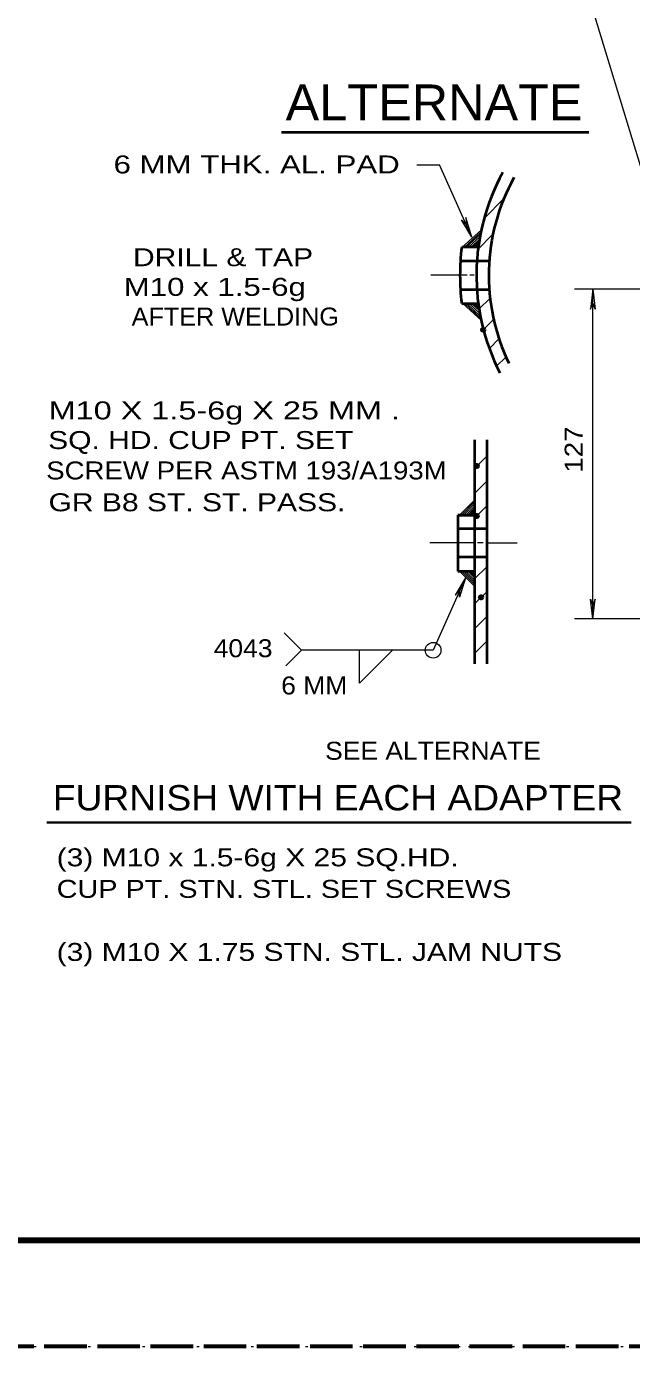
# Model space of a CAD drawing. Extents: x 312583 to 312854, y 144419 to 144597.
# Drawn here: x 312617.4 to 312643.1, y 144418.6 to 144474.4 of the extents above; entities that cross this region are included whole.
import ezdxf
from ezdxf.enums import TextEntityAlignment as Align

# ---------------------------------------------------------------- set-up
doc = ezdxf.new("R2010")
doc.units = 0
doc.header["$LTSCALE"] = 0.3
doc.header["$PDMODE"] = 32
doc.header["$PDSIZE"] = 0.15
doc.linetypes.add('DOTTED', pattern=[1.5, 0.3, -1.2])
doc.linetypes.add('LONG_DASHED', pattern=[7.5, 6, -1.5])
for name, color, linetype, lineweight in [('1', 7, 'Continuous', 40), ('2', 7, 'Continuous', 13), ('63', 7, 'DOTTED', 13)]:
    doc.layers.add(name, color=color, linetype=linetype, lineweight=lineweight)

msp = doc.modelspace()

# ---------------------------------------------------------------- linework, layer by layer
at = {"layer": '1', "lineweight": 25}
for p, q in [((312636.8151, 144466.3156), (312637.6508, 144467.1513)), ((312635.8875, 144465.0966), (312636.7001, 144465.825)), ((312635.9795, 144465.0966), (312636.6771, 144465.733)), ((312636.0561, 144465.0966), (312636.6618, 144465.641)), ((312636.1558, 144465.0966), (312636.6388, 144465.5336)), ((312636.5545, 144465.0046), (312637.1908, 144465.641)), ((312636.2555, 144465.0966), (312636.6158, 144465.4263)), ((312636.6081, 144462.4823), (312637.0681, 144462.9423)), ((312635.9105, 144462.72), (312636.7001, 144461.9916)), ((312636.0025, 144462.72), (312636.6771, 144462.0836)), ((312636.0791, 144462.72), (312636.6541, 144462.1833)), ((312636.1865, 144462.72), (312636.6388, 144462.2906)), ((312636.2785, 144462.72), (312636.6158, 144462.398)), ((312636.7845, 144461.6083), (312637.2215, 144462.0453)), ((312637.0375, 144460.8033), (312637.4438, 144461.2173)), ((312637.3441, 144460.0673), (312637.7428, 144460.4583)), ((312636.4043, 144455.7356), (312636.9257, 144456.2493)), ((312636.4043, 144454.6776), (312636.9257, 144455.199)), ((312635.7757, 144453.7653), (312636.4043, 144454.394)), ((312635.86, 144453.7653), (312636.4043, 144454.3173)), ((312635.9367, 144453.7653), (312636.4043, 144454.233)), ((312636.0363, 144453.7653), (312636.4043, 144454.141)), ((312636.1283, 144453.7653), (312636.4043, 144454.049)), ((312636.4043, 144453.6273), (312636.9257, 144454.1486)), ((312636.4043, 144451.059), (312636.9257, 144451.5726)), ((312635.768, 144451.3886), (312636.4043, 144450.76)), ((312635.8523, 144451.3886), (312636.4043, 144450.8443)), ((312635.9367, 144451.3886), (312636.4043, 144450.921)), ((312636.0287, 144451.3886), (312636.4043, 144451.013)), ((312636.1207, 144451.3886), (312636.4043, 144451.1126)), ((312636.4043, 144450.001), (312636.9257, 144450.5223)), ((312636.4043, 144448.9506), (312636.9257, 144449.472)), ((312636.4043, 144447.9003), (312636.9257, 144448.4216))]:
    msp.add_line(p, q, dxfattribs=at)
at = {"layer": '1', "lineweight": 35}
for p, q in [((312636.3398, 144465.0966), (312636.6081, 144465.342)), ((312636.4395, 144465.0966), (312636.5851, 144465.2423)), ((312636.5315, 144465.0966), (312636.5775, 144465.1426)), ((312636.3628, 144462.72), (312636.6005, 144462.49)), ((312636.4548, 144462.72), (312636.5851, 144462.5896)), ((312636.5468, 144462.72), (312636.5698, 144462.697)), ((312636.205, 144453.7653), (312636.4043, 144453.9646)), ((312636.297, 144453.7653), (312636.4043, 144453.8726)), ((312636.389, 144453.7653), (312636.4043, 144453.7883)), ((312636.1973, 144451.3886), (312636.3967, 144451.1893)), ((312636.2893, 144451.3886), (312636.4043, 144451.2813)), ((312636.3813, 144451.3886), (312636.4043, 144451.3733))]:
    msp.add_line(p, q, dxfattribs=at)
at = {"layer": '1'}
for p, q in [((312637.0298, 144464.4986), (312635.8108, 144464.4986)), ((312637.0375, 144463.295), (312635.8108, 144463.295)), ((312635.8721, 144462.72), (312636.5698, 144462.72)), ((312636.9257, 144456.9393), (312636.9257, 144447.471)), ((312635.7067, 144453.7653), (312636.4043, 144453.7653)), ((312636.9257, 144453.1826), (312635.7067, 144453.1826)), ((312636.9257, 144451.9866), (312635.7067, 144451.9866)), ((312635.7067, 144451.3886), (312636.4043, 144451.3886))]:
    msp.add_line(p, q, dxfattribs=at)
at = {"layer": '1', "lineweight": 158}
msp.add_line((312616.5, 144423.0846), (312849, 144423.0846), dxfattribs=at)
at = {"layer": '1'}
msp.add_lwpolyline([(312636.4043, 144456.9393), (312636.4043, 144452.5846), (312636.4043, 144447.471)], dxfattribs=at)
at = {"layer": '1', "lineweight": 25}
msp.add_lwpolyline([(312636.1283, 144453.7653), (312636.4043, 144453.7653), (312636.4043, 144454.049)], close=True, dxfattribs=at)
at = {"layer": '1'}
for radius, start, end in [(9.0606, 151.31152, 207.07224), (8.5393, 151.05958, 205.78809), (9.7576, 172.98875, 187.01125)]:
    msp.add_arc((312645.5516, 144463.9069), radius, start, end, dxfattribs=at)
for p in [(312636.7768, 144461.6006), (312636.504, 144455.8353), (312636.504, 144453.727), (312636.688, 144450.2846)]:
    msp.add_point(p, dxfattribs=at)
at = {"layer": '2'}
for p, q in [((312644.8159, 144463.9808), (312639.6916, 144480.8177)), ((312633.9708, 144468.585), (312634.9291, 144468.585)), ((312636.3015, 144465.526), (312634.9291, 144468.585)), ((312635.8645, 144466.2543), (312636.0638, 144466.0473)), ((312636.3015, 144465.526), (312635.8645, 144466.2543)), ((312636.0485, 144466.3463), (312636.0638, 144466.0473)), ((312636.3015, 144465.526), (312636.0485, 144466.3463)), ((312636.0945, 144463.9083), (312634.5611, 144463.9083)), ((312636.4011, 144463.9083), (312636.2095, 144463.9083)), ((312645.8431, 144463.3144), (312640.6365, 144463.3144)), ((312641.4143, 144463.3144), (312641.3147, 144462.4787)), ((312641.4143, 144449.3764), (312641.4143, 144463.3144)), ((312641.4143, 144463.3144), (312641.514, 144462.4787)), ((312641.3147, 144462.4787), (312641.4143, 144462.7471)), ((312641.514, 144462.4787), (312641.4143, 144462.7471)), ((312636.389, 144452.5846), (312634.5183, 144452.5846)), ((312636.78, 144452.5846), (312636.5423, 144452.5846)), ((312636.9333, 144452.5846), (312638.2213, 144452.5846)), ((312636.0287, 144451.105), (312635.584, 144450.3766)), ((312636.0287, 144451.105), (312635.7757, 144450.2846)), ((312635.584, 144450.3766), (312635.791, 144450.5836)), ((312635.7757, 144450.2846), (312635.791, 144450.5836)), ((312641.3147, 144450.2121), (312641.4143, 144449.9437)), ((312641.4143, 144449.3764), (312641.3147, 144450.2121)), ((312641.514, 144450.2121), (312641.4143, 144449.9437)), ((312641.4143, 144449.3764), (312641.514, 144450.2121)), ((312646.5407, 144449.3764), (312640.6365, 144449.3764)), ((312629.0827, 144448.046), (312628.3543, 144448.7743)), ((312629.0827, 144448.046), (312628.4233, 144447.3866))]:
    msp.add_line(p, q, dxfattribs=at)
at = {"layer": '2', "lineweight": 40}
for p, q in [((312628.2461, 144469.965), (312641.2504, 144469.965)), ((312636.5698, 144465.0966), (312635.8721, 144465.0966)), ((312636.4043, 144453.7653), (312635.7067, 144453.7653)), ((312635.7067, 144453.7653), (312635.7067, 144451.3886))]:
    msp.add_line(p, q, dxfattribs=at)
at = {"layer": '2', "lineweight": 35}
msp.add_line((312618.3088, 144440.7596), (312643.0408, 144440.7596), dxfattribs=at)
at = {"layer": '2'}
for points in [[(312636.0287, 144451.105), (312634.6563, 144448.046), (312629.0827, 144448.046)], [(312632.9313, 144448.046), (312631.536, 144446.6506), (312631.536, 144448.046)]]:
    msp.add_lwpolyline(points, dxfattribs=at)
msp.add_circle((312634.6563, 144448.0439), 0.3332, dxfattribs=at)
at = {"layer": '63', "linetype": 'LONG_DASHED', "lineweight": 60}
msp.add_line((312851.75, 144418.5846), (312583.526, 144418.5846), dxfattribs=at)
at = {"layer": '63'}
msp.add_lwpolyline([(312601.2, 144418.5846), (312853.5, 144418.5846), (312853.5, 144596.7846)], dxfattribs=at)

# ---------------------------------------------------------------- texts
at = {"layer": '2'}
for s, height, width, p in [('ALTERNATE', 1.52, 1.05, (312634.6984, 144470.4596)), ('FURNISH WITH EACH ADAPTER', 1.07, 1.1, (312630.6286, 144441.269))]:
    msp.add_text(s, height=height, dxfattribs=dict(at, width=width)).set_placement(p, align=Align.CENTER)
for s, width, p in [(' 6 MM THK. AL. PAD', 1.3, (312620.7638, 144468.2165)), ('DRILL & TAP', 1.25, (312621.9535, 144464.2921)), (' M10 x 1.5-6g', 1.3, (312621.1942, 144463.0376)), ('AFTER WELDING', 1.05, (312621.8969, 144461.7812)), ('M10 X 1.5-6g X 25 MM .', 1.35, (312618.3844, 144457.811)), ('SQ. HD. CUP PT. SET', 1.25, (312618.3624, 144456.5565)), ('SCREW PER ASTM 193/A193M', 1.15, (312618.2806, 144455.2703)), ('GR B8 ST. ST. PASS.', 1.25, (312618.3795, 144453.9239)), ('4043', 1.1, (312625.3708, 144447.7493)), ('6 MM', 1.1, (312628.227, 144446.1748)), ('SEE ALTERNATE', 1.1, (312630.0873, 144443.4112)), ('(3) M10 x 1.5-6g X 25 SQ.HD.', 1.25, (312618.7228, 144438.9032)), ('CUP PT. STN. STL. SET SCREWS', 1.2, (312618.7228, 144437.5692)), ('(3) M10 X 1.75 STN. STL. JAM NUTS', 1.25, (312618.7228, 144434.9012))]:
    msp.add_text(s, height=0.76, dxfattribs=dict(at, width=width)).set_placement(p)
at = {"layer": '2', "width": 1.15}
msp.add_text('127 ', height=0.76, rotation=90, dxfattribs=at).set_placement((312640.9856, 144455.5587))

doc.saveas('drawing.dxf')
